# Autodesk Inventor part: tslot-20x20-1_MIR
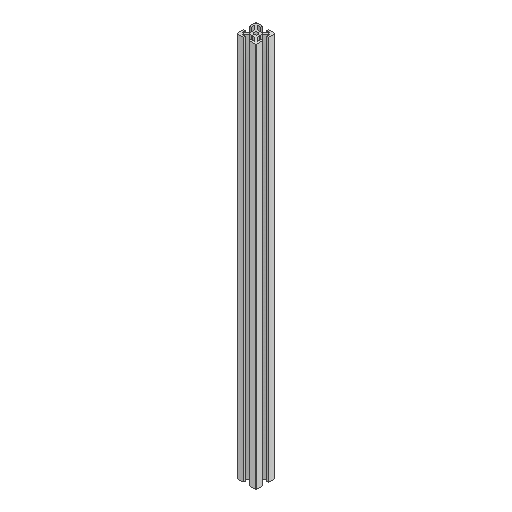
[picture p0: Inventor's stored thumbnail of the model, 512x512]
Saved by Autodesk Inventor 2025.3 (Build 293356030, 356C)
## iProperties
Created: 2025-03
Part Number: tslot-20x20-1_MIR
Material: Generico
Document SubType Name: Modeling
Designer: R5800u
Density: 1 g/cm^3
Appearance: Default
Author: Ryzen5700u
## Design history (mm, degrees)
derived "tslot-20x20-1.ipt"
  sketch "Schizzo1"
    geometry: L1 (-3.761, -16)-(-4.7, -16) reference; L2 (-3.761, -16)-(-0.7, -12.939) reference; L3 (-0.7, -12.939)-(-0.7, -10.52) reference; L4 (-0.4, -10)-(-0.7, -10.52) reference; L5 (-0.4, -10)-(-0.7, -9.48) reference; L6 (-0.7, -7.061)-(-0.7, -9.48) reference; L7 (-3.761, -4)-(-0.7, -7.061) reference; L8 (-3.761, -4)-(-4.7, -4) reference; L9 (-4.7, -4)-(-4.7, -7) reference; L10 (-4.7, -7)-(-6.4, -7) reference; L11 (-6.7, -6.7)-(-6.7, -1) reference; L12 (-5.7, 0)-(0, 0) reference; L13 (0.3, -2)-(0.3, -0.3) reference; L14 (-2.7, -2)-(0.3, -2) reference; L15 (-2.7, -2.939)-(-2.7, -2) reference; L16 (-2.7, -2.939)-(0.361, -6) reference; L17 (0.361, -6)-(2.78, -6) reference; L18 (3.3, -6.3)-(2.78, -6) reference; L19 (3.3, -6.3)-(3.82, -6) reference; L20 (6.239, -6)-(3.82, -6) reference; L21 (9.3, -2.939)-(6.239, -6) reference; L22 (9.3, -2.939)-(9.3, -2) reference; L23 (9.3, -2)-(6.3, -2) reference; L24 (6.3, -2)-(6.3, -0.3) reference; L25 (12.3, 0)-(6.6, 0) reference; L26 (13.3, -6.7)-(13.3, -1) reference; L27 (11.3, -7)-(13, -7) reference; L28 (11.3, -4)-(11.3, -7) reference; L29 (10.361, -4)-(11.3, -4) reference; L30 (10.361, -4)-(7.3, -7.061) reference; L31 (7.3, -7.061)-(7.3, -9.48) reference; L32 (7, -10)-(7.3, -9.48) reference; L33 (7, -10)-(7.3, -10.52) reference; L34 (7.3, -12.939)-(7.3, -10.52) reference; L35 (10.361, -16)-(7.3, -12.939) reference; L36 (10.361, -16)-(11.3, -16) reference; L37 (11.3, -16)-(11.3, -13) reference; L38 (11.3, -13)-(13, -13) reference; L39 (13.3, -13.3)-(13.3, -19) reference; L40 (12.3, -20)-(6.6, -20) reference; L41 (6.3, -18)-(6.3, -19.7) reference; L42 (9.3, -18)-(6.3, -18) reference; L43 (9.3, -17.061)-(9.3, -18) reference; L44 (9.3, -17.061)-(6.239, -14) reference; L45 (6.239, -14)-(3.82, -14) reference; L46 (3.3, -13.7)-(3.82, -14) reference; L47 (3.3, -13.7)-(2.78, -14) reference; L48 (0.361, -14)-(2.78, -14) reference; L49 (-2.7, -17.061)-(0.361, -14) reference; L50 (-2.7, -17.061)-(-2.7, -18) reference; L51 (-2.7, -18)-(0.3, -18) reference; L52 (0.3, -18)-(0.3, -19.7) reference; L53 (-5.7, -20)-(0, -20) reference; L54 (-6.7, -13.3)-(-6.7, -19) reference; L55 (-4.7, -13)-(-6.4, -13) reference; L56 (-4.7, -16)-(-4.7, -13) reference; C1 r 2.1 at (3.3, -10) reference; A1 r 0.3 centre (-6.4, -6.7) between (-6.7, -6.7) and (-6.4, -7) reference; A2 r 1 centre (-5.7, -1) between (-5.7, 0) and (-6.7, -1) reference; A3 r 0.3 centre (0, -0.3) between (0.3, -0.3) and (0, 0) reference; A4 r 0.3 centre (6.6, -0.3) between (6.6, 0) and (6.3, -0.3) reference; A5 r 1 centre (12.3, -1) between (13.3, -1) and (12.3, 0) reference; A6 r 0.3 centre (13, -6.7) between (13, -7) and (13.3, -6.7) reference; A7 r 0.3 centre (13, -13.3) between (13.3, -13.3) and (13, -13) reference; A8 r 1 centre (12.3, -19) between (12.3, -20) and (13.3, -19) reference; A9 r 0.3 centre (6.6, -19.7) between (6.3, -19.7) and (6.6, -20) reference; A10 r 0.3 centre (0, -19.7) between (0, -20) and (0.3, -19.7) reference; A11 r 1 centre (-5.7, -19) between (-6.7, -19) and (-5.7, -20) reference; A12 r 0.3 centre (-6.4, -13.3) between (-6.4, -13) and (-6.7, -13.3) reference; 1 further point
feature "Solido1::tslot-20x20-1.ipt" dims "d0" = 10
tag "Lavorazione contrassegno1"
node "Solido1"
